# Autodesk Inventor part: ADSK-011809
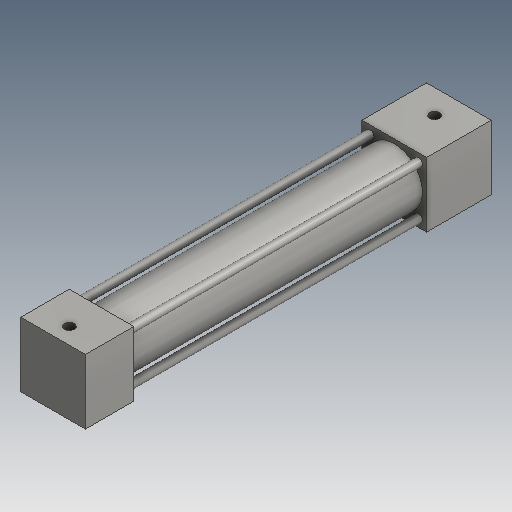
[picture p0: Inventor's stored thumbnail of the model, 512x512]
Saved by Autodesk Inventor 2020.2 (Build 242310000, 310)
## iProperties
Created: 1999-12
Part Number: ADSK-011809
Material: Aluminum
Description: SLIDE CYLINDER_SD22X4.0
Document SubType Name: Modeling
Designer: glanglot
Density: 2.71 g/cm^3
Appearance: Steel
Mass: 207.685 g
Surface Area: 192.024 cm^2
Volume: 76.6363 cm^3
Control State: 0
Master: False
Checked Out: False
Shininess: 0.0
Length Units: 11272
Angle Units: 11279
Time Units: 11290
Mass Units: 11286
Length Display Precision: 3
Angle Display Precision: 2
Compacted: True
Dimensions: 1x6,3x1 in
Mass: 0,458 lb
VLT_Material: Aluminum
Density: 0.0
Volumn: 0.0
Area: 0.0
PropertySet Name: Model Information
Author: glanglot
Revision Number: -
Title: SLIDE CYLINDER_SD22X4.0
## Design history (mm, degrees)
node "Extrusion1" dims "d2" = 25.4, "d3" = 0
node "Extrusion2" dims "d7" = 115.062, "d8" = 0
node "Extrusion3" dims "d9" = 19.05, "d10" = 0
node "Hole1" dims "d14" = 3.9624, "d15" = 9.525, "d16" = 6.35, "d17" = 60 deg, "d18" = 12.7, "d19" = 118 deg
node "Extrusion4" dims "d32" = 12.7, "d33" = 0
node "Solide1"
node "Corps solides"
node "Corps surfaciques"
sketch "Sketch1"
  geometry: L1 (0, 25.4)-(25.4, 25.4); L2 (25.4, 25.4)-(25.4, 0); L3 (25.4, 0)-(0, 0); L4 (0, 0)-(0, 25.4); 1 further point
  constraints: 8 end point, 2 parallel, 1 coincident, 1 horizontal, 1 perpendicular
  dimensions: "d0" = 25.4 distance of L1.start L1.end; "d1" = 25.4 distance of L3.end L1.start (= d0)
sketch "Sketch2"
  geometry: L1 (0, 25.4)-(25.4, 25.4) reference; L2 (0, 0)-(0, 25.4) reference; C1 r 11.112 at (12.7, 12.7)
  constraints: 1 centre point
  dimensions: "d4" = 12.7 distance from line of C1.centre L2; "d5" = 12.7 distance from line of C1.centre L1 (= d4); "d6" = 22.225 diameter of C1
sketch "Sketch4"
  geometry: L1 (-12.7, 12.7)-(12.7, 12.7) reference; L2 (-12.7, -12.7)-(-12.7, 12.7) reference; L3 (12.7, -12.7)-(-12.7, -12.7) reference; L4 (12.7, 12.7)-(12.7, -12.7) reference
sketch "Sketch5"
  geometry: L1 (25.4, 0)-(0, 0) reference; L2 (0, 0)-(0, -25.4) reference; L3 (0, -159.512)-(25.4, -159.512) reference; 2 further points
  constraints: 1 vertical alignment
  dimensions: "d11" = 12.7 distance from line of point (12.7, -9.525) L2; "d12" = 9.525 distance from line of point (12.7, -9.525) L1; "d13" = 6.35 distance from line of L3 point (12.7, -153.162)
sketch "Sketch6"
  geometry: L1 (0, 25.4)-(25.4, 25.4) reference; L2 (0, 0)-(0, 25.4) reference; L3 (25.4, 0)-(0, 0) reference; L4 (25.4, 25.4)-(25.4, 0) reference; C1 r 1.587 at (3.175, 22.225); C2 r 1.587 at (22.225, 22.225); C3 r 1.587 at (22.225, 3.175); C4 r 1.587 at (3.175, 3.175)
  constraints: 4 centre point
  dimensions: "d20" = 3.175 diameter of C1; "d22" = 3.175 distance from line of C1.centre L1 (= d21); "d23" = 3.175 diameter of C2 (= d20); "d24" = 3.175 distance from line of L1 C2.centre (= d21); "d26" = 3.175 distance from line of L2 C4.centre (= d21); "d28" = 3.175 diameter of C4 (= d20); "d29" = 3.175 diameter of C3 (= d20); "d30" = 3.175 distance from line of L4 C3.centre (= d21); "d31" = 3.175 distance from line of L3 C3.centre (= d21); "d34" = 3.175 distance from line of L4 C2.centre (= d21); "d37" = 3.175 distance from line of C4.centre L3 (= d21); "d38" = 3.175 distance from line of C1.centre L2 (= d21)
other parameters: "d21" = 3.175
